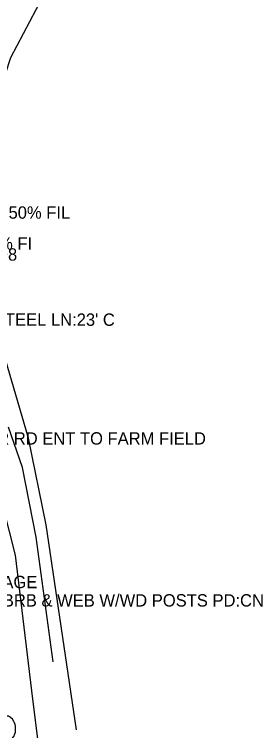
# Model space of a CAD drawing. Extents: x 1451369 to 1458940, y 1868647 to 1875095.
# Drawn here: x 1454943 to 1455040.9, y 1871712 to 1872001.9 of the extents above; entities that cross this region are included whole.
import ezdxf

# ---------------------------------------------------------------- set-up
doc = ezdxf.new("R2010")
doc.units = 0
for name, color, linetype in [('E_ROW Point Number', 7, 'Continuous'), ('E_Tract Residual', 7, 'Continuous'), ('S_BUILDING_ANNOT', 7, 'Continuous'), ('S_FENCE_ANNOT', 7, 'Continuous'), ('S_MISC_BOUNDARY', 7, 'Continuous'), ('S_SIDE_DRAIN_ANNOT', 7, 'Continuous'), ('S_SURVEY_TEXT_ANNOT', 7, 'Continuous'), ('S_TRAILS', 7, 'Continuous')]:
    doc.layers.add(name, color=color, linetype=linetype)

msp = doc.modelspace()

# ---------------------------------------------------------------- linework, layer by layer
at = {"layer": 'E_ROW Point Number'}
msp.add_ellipse((1454940.13, 1871712.95), major_axis=(-0.41, 4.94), ratio=0.685291, start_param=3.141563, end_param=6.283156, dxfattribs=at)
at = {"layer": 'E_Tract Residual'}
msp.add_lwpolyline([(1454958.72, 1871739.79), (1454951.87, 1871790.34), (1454946.35, 1871818.45), (1454940.67, 1871834.81)], dxfattribs=at)
at = {"layer": 'S_MISC_BOUNDARY'}
msp.add_lwpolyline([(1454968.19, 1871712.29), (1454955.87, 1871795.22), (1454948.77, 1871830.35), (1454936.8, 1871870.9), (1454929.34, 1871910.01), (1454929.36, 1871947.22), (1454941.55, 1871984.39), (1454964.58, 1872028.21), (1455009.26, 1872095.69), (1455071.49, 1872183.66), (1455110.31, 1872228.42), (1455136.38, 1872254.42), (1455148.95, 1872271.07), (1455155.24, 1872298.12), (1455196.69, 1872380.74)], dxfattribs=at)
at = {"layer": 'S_TRAILS'}
msp.add_lwpolyline([(1454932.3, 1871821.77), (1454936.1, 1871811.22), (1454943.39, 1871782.97), (1454949.94, 1871728.11), (1454956.19, 1871678.16)], dxfattribs=at)

# ---------------------------------------------------------------- texts
at = {"layer": 'S_BUILDING_ANNOT'}
msp.add_text('1STRY WD W/TIN RF STORAGE', height=5, dxfattribs=at).set_placement((1454851.63, 1871769.64))
at = {"layer": 'S_FENCE_ANNOT'}
msp.add_text('3STR BRB & WEB W/WD POSTS PD:CN:POOR', height=5, dxfattribs=at).set_placement((1454919.43, 1871762.21))
at = {"layer": 'S_SIDE_DRAIN_ANNOT'}
for s, p in [('DI:36" TY:CMP LN:21\' CN:50% FIL', (1454860.85, 1871919.16)), ('DI:24" TY:CMP LN:20\' CN:100% FI', (1454845.49, 1871906.64)), ('CN:50% FILLED BOTH SH:8.98', (1454848.29, 1871902.18)), ('DI:18" TY:CMP TY:STEEL LN:23\' C', (1454877.04, 1871875.81))]:
    msp.add_text(s, height=5, dxfattribs=at).set_placement(p)
at = {"layer": 'S_SURVEY_TEXT_ANNOT'}
msp.add_text('GR RD ENT TO FARM FIELD', height=5, dxfattribs=at).set_placement((1454930.91, 1871827.74))

doc.saveas('drawing.dxf')
